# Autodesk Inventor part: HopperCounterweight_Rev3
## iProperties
Created: 2009-01
Part Number: HopperCounterweight_Rev3
Document SubType Name: Modeling
Designer: claivier
Material: Acier
Norme de conversion: STEP AP214IS
Nom du fichier: HopperCounterweight_Rev3.STEP
Préprocesseur: SolidWorks 2008
Postprocesseur: Build: 344a, Release: 11 SP2 - Date: Fri 08/18/2006
Unités envoyées: INCHES
Incertitude: 1e-05
Author: claivier
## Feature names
1. Base1
